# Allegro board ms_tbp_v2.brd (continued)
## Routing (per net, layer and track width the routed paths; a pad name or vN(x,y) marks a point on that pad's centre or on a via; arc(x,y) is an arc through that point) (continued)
PCIE_T2B_B1_RX_DN<13>: length 45.3
  TOP w0.127: J2.44 v1(46.11,13.96)
  LYR3 w0.127: J1.E3 26.55,9.79 26.79,9.79 26.87,9.87 26.87,26.2 27.46,26.78 31.45,26.78 33.43,24.8 33.43,21.85 41,14.28 42.91,14.28 43.08,14.11 43.72,13.47 45.62,13.47 v1(46.11,13.96)
PCIE_T2B_B1_RX_DN<14>: length 40.4
  TOP w0.127: J2.27 v1(44.84,11.42)
  LYR3 w0.127: J1.F2 28.55,11.09 28.77,11.09 28.87,11.18 28.87,24.91 29.45,25.49 30.51,25.49 30.75,25.49 32,24.25 32,20.43 41.49,10.93 44.35,10.93 v1(44.84,11.42)
PCIE_T2B_B1_RX_DN<15>: length 20.3
  TOP w0.127: J2.12 v1(46.11,8.88)
  LYR3 w0.127: J1.E1 30.55,9.79 30.91,9.79 35.02,5.68 41.8,5.68 44.51,8.39 45.62,8.39 v1(46.11,8.88)
PCIE_T2B_B1_RX_DP<0>: length 53.3
  TOP w0.127: J2.113 42.45,25.24 41.73,25.24 40.95,26.02 40.95,26.82 35.17,32.6 22.88,32.6 17.16,26.88 17.16,6.96 16.79,6.59 16.55,6.59 J1.B8
PCIE_T2B_B1_RX_DP<1>: length 54.2
  TOP w0.127: J1.A7 18.55,5.29 18.8,5.29 19.16,5.65 19.16,26.49 24.05,31.38 34.34,31.38 39.49,26.23 39.49,24.6 41.39,22.7 43.72,22.7 J2.98
PCIE_T2B_B1_RX_DP<2>: length 49.6
  TOP w0.127: J1.B6 20.55,6.59 20.8,6.59 21.15,6.94 21.15,26.36 24.95,30.16 33.57,30.16 38.23,25.5 38.23,23.8 41.86,20.16 42.45,20.16 J2.81
PCIE_T2B_B1_RX_DP<3>: length 50.6
  TOP w0.127: J1.A5 22.55,5.29 22.8,5.29 23.15,5.63 23.15,26.14 25.95,28.94 32.75,28.94 35.49,26.21 35.49,23.79 37.19,22.09 37.19,22.09 41.66,17.62 43.72,17.62 J2.66
PCIE_T2B_B1_RX_DP<4>: length 46
  TOP w0.127: J2.49 42.43,15.1 42.02,15.1 40.8,16.32 40.8,16.7 37.02,20.49 34.04,23.46 34.04,25.93 32.25,27.72 27.14,27.72 25.15,25.73 25.15,6.94 24.8,6.59 24.55,6.59 J1.B4
PCIE_T2B_B1_RX_DP<5>: length 49.6
  TOP w0.127: J2.34 43.72,12.54 41.68,12.54 40.86,13.35 40.86,14.14 38.2,16.8 34.53,16.8 32.65,18.68 32.65,25.6 31.77,26.48 28.35,26.48 27.65,26.48 27.16,25.99 27.16,25.92 27.16,25.92 27.16,5.65 26.8,5.29 26.55,5.29 J1.A3
PCIE_T2B_B1_RX_DP<6>: length 44.6
  TOP w0.127: J1.B2 28.55,6.59 28.8,6.59 29.16,6.95 29.16,24.75 29.63,25.21 30.8,25.21 31.31,24.7 31.31,18.24 34.09,15.46 37.67,15.46 39.94,13.19 39.94,12.56 40.77,11.72 40.77,10.55 41.33,10 42.45,10 J2.17
PCIE_T2B_B1_RX_DP<7>: length 15.5
  TOP w0.127: J1.A1 30.55,5.29 39.42,5.29 41.59,7.46 43.72,7.46 J2.2
PCIE_T2B_B1_RX_DP<8>: length 50.5
  TOP w0.127: J2.115 v1(44.84,25.39)
  LYR3 w0.127: v1(44.84,25.39) 44.35,25.88 41.66,25.88 35.85,31.69 21.91,31.69 17.13,26.91 17.13,12.57 17.1,12.54 17.1,11.09 16.8,10.79 16.55,10.79 J1.E8
PCIE_T2B_B1_RX_DP<9>: length 51.2
  TOP w0.127: J2.100 v1(46.11,22.85)
  LYR3 w0.127: J1.D7 18.55,9.49 18.82,9.49 19.14,9.81 19.14,26.87 22.93,30.66 34.76,30.66 41.16,24.26 42.48,24.26 43.4,23.34 45.62,23.34 v1(46.11,22.85)
PCIE_T2B_B1_RX_DP<10>: length 47
  TOP w0.127: J2.83 v1(44.84,20.31)
  LYR3 w0.127: v1(44.84,20.31) 44.35,20.8 42.01,20.8 37.71,25.1 37.71,25.99 34.07,29.63 24.57,29.63 21.13,26.19 21.13,11.12 20.8,10.79 20.55,10.79 J1.E6
PCIE_T2B_B1_RX_DP<11>: length 47.9
  TOP w0.127: J2.68 v1(46.11,17.77)
  LYR3 w0.127: v1(46.11,17.77) 45.62,18.26 43.23,18.26 42.43,19.06 41.55,19.06 35.86,24.75 35.86,25.75 33.02,28.59 25.51,28.59 23.16,26.24 23.16,9.77 22.89,9.49 22.55,9.49 J1.D5
PCIE_T2B_B1_RX_DP<12>: length 44.2
  TOP w0.127: J2.51 v1(44.84,15.23)
  LYR3 w0.127: J1.E4 24.55,10.79 24.8,10.79 25.16,11.15 25.16,25.93 26.78,27.55 32.13,27.55 34.31,25.37 34.31,22.77 41.36,15.72 44.35,15.72 v1(44.84,15.23)
PCIE_T2B_B1_RX_DP<13>: length 45.3
  TOP w0.127: J2.36 v1(46.11,12.69)
  LYR3 w0.127: J1.D3 26.55,9.49 26.91,9.49 27.16,9.75 27.16,26.07 27.58,26.49 31.32,26.49 33.14,24.68 33.14,21.73 40.88,13.99 42.79,13.99 43.6,13.18 45.62,13.18 v1(46.11,12.69)
PCIE_T2B_B1_RX_DP<14>: length 40.4
  TOP w0.127: J2.19 v1(44.84,10.15)
  LYR3 w0.127: v1(44.84,10.15) 44.35,10.64 41.37,10.64 31.7,20.31 31.7,24.12 30.63,25.2 29.57,25.2 29.16,24.79 29.16,11.06 28.89,10.79 28.55,10.79 J1.E2
PCIE_T2B_B1_RX_DP<15>: length 20.3
  TOP w0.127: J2.4 v1(46.11,7.61)
  LYR3 w0.127: v1(46.11,7.61) 45.62,8.1 44.63,8.1 41.92,5.39 34.9,5.39 30.79,9.49 30.55,9.49 J1.D1
PCIE_T2B_B2_RX_DN<0>: length 53.2
  TOP w0.127: J13.C8 237.55,6.89 237.66,6.89 237.85,7.08 237.85,26.46 244.56,33.17 256.03,33.17 262.26,26.95 262.26,26.15 262.86,25.54 263.45,25.54 J14.121
PCIE_T2B_B2_RX_DN<1>: length 54.3
  TOP w0.127: J13.B7 239.55,5.59 239.67,5.59 239.85,5.77 239.85,26.61 245.09,31.85 255.31,31.85 260.62,26.53 260.8,26.36 260.8,24.72 262.52,23 264.72,23 J14.106
PCIE_T2B_B2_RX_DN<2>: length 49.5
  TOP w0.127: J13.C6 241.55,6.89 241.67,6.89 241.85,7.06 241.85,26.49 245.9,30.55 254.61,30.55 259.53,25.63 259.53,24.21 263.27,20.46 263.45,20.46 J14.89
PCIE_T2B_B2_RX_DN<3>: length 50.9
  TOP w0.127: J13.B5 243.55,5.59 243.67,5.59 243.84,5.76 243.84,26.26 246.89,29.32 253.81,29.32 256.78,26.35 256.78,24.9 261.73,19.95 261.73,18.43 262.24,17.92 264.72,17.92 J14.74
PCIE_T2B_B2_RX_DN<4>: length 46.3
  TOP w0.127: J13.C4 245.55,6.89 245.67,6.89 245.85,7.07 245.85,25.86 248.07,28.08 253.32,28.08 255.38,26.03 255.38,24.52 260.31,19.6 260.31,17.85 262.77,15.38 263.45,15.38 J14.57
PCIE_T2B_B2_RX_DN<5>: length 48.7
  TOP w0.127: J14.42 264.72,12.84 263.58,12.84 262.44,13.98 262.44,13.99 259.3,17.13 256.45,17.13 253.93,19.65 253.93,22.5 253.93,22.5 253.93,25.75 252.9,26.78 249.47,26.78 248.53,26.78 247.86,26.11 247.86,26.05 247.86,26.04 247.86,5.77 247.67,5.59 247.55,5.59 J13.B3
PCIE_T2B_B2_RX_DN<6>: length 44
  TOP w0.127: J13.C2 249.55,6.89 249.67,6.89 249.86,7.07 249.86,24.87 250.5,25.52 251.92,25.52 252.62,24.82 252.62,19.11 255.82,15.91 258.64,15.91 261.88,12.68 261.88,11.21 262.79,10.3 263.45,10.3 J14.25
PCIE_T2B_B2_RX_DN<7>: length 15.5
  TOP w0.127: J13.B1 251.55,5.59 260.29,5.59 262.46,7.76 264.72,7.76 J14.10
PCIE_T2B_B2_RX_DN<8>: length 51.6
  TOP w0.127: J14.123 v1(265.84,26.66)
  LYR3 w0.127: v1(265.84,26.66) 265.35,26.17 262.78,26.17 255.64,33.31 244.12,33.31 237.84,27.03 237.84,11.24 237.68,11.09 237.55,11.09 J13.F8
PCIE_T2B_B2_RX_DN<9>: length 52.1
  TOP w0.127: J14.108 v1(267.11,24.12)
  LYR3 w0.127: J13.E7 239.55,9.79 239.7,9.79 239.85,9.94 239.85,26.99 244.84,31.98 254.85,31.98 262.28,24.55 263.6,24.55 264.52,23.63 266.62,23.63 v1(267.11,24.12)
PCIE_T2B_B2_RX_DN<10>: length 47.5
  TOP w0.127: J14.91 v1(265.84,21.58)
  LYR3 w0.127: J13.F6 241.55,11.09 241.68,11.09 241.84,11.24 241.84,26.31 246.13,30.61 254.51,30.61 258.83,26.29 259,26.12 259,25.22 263.13,21.09 265.35,21.09 v1(265.84,21.58)
PCIE_T2B_B2_RX_DN<11>: length 48.5
  TOP w0.127: J14.76 v1(267.11,19.04)
  LYR3 w0.127: v1(267.11,19.04) 266.62,18.55 263.84,18.55 259.49,22.9 258.74,22.9 257.36,24.28 257.36,25.66 253.59,29.43 246.93,29.43 243.87,26.36 243.87,9.89 243.76,9.79 243.55,9.79 J13.E5
PCIE_T2B_B2_RX_DN<12>: length 44
  TOP w0.127: J14.59 v1(265.84,16.5)
  LYR3 w0.127: J13.F4 245.55,11.09 245.68,11.09 245.87,11.27 245.87,26.05 247.74,27.93 253.16,27.93 256.04,25.05 256.21,24.88 256.21,22.78 262.98,16.01 265.35,16.01 v1(265.84,16.5)
PCIE_T2B_B2_RX_DN<13>: length 45.4
  TOP w0.127: J14.44 v1(267.11,13.96)
  LYR3 w0.127: v1(267.11,13.96) 266.62,13.47 262.82,13.47 261.4,14.9 261.39,14.9 254.91,21.38 254.91,24.32 254.74,24.49 252.35,26.88 248.56,26.88 247.87,26.2 247.87,9.87 247.79,9.79 247.55,9.79 J13.E3
PCIE_T2B_B2_RX_DN<14>: length 40.2
  TOP w0.127: J14.27 v1(265.84,11.42)
  LYR3 w0.127: v1(265.84,11.42) 265.35,10.93 262.88,10.93 253,20.81 253,24.25 251.75,25.49 251.51,25.49 250.45,25.49 249.87,24.91 249.87,11.18 249.77,11.09 249.55,11.09 J13.F2
PCIE_T2B_B2_RX_DN<15>: length 20.9
  TOP w0.127: J14.12 v1(267.11,8.88)
  LYR3 w0.127: v1(267.11,8.88) 266.62,8.39 265.5,8.39 262.79,5.68 255.09,5.68 252.59,8.18 252.59,9.27 252.08,9.79 251.55,9.79 J13.E1
PCIE_T2B_B2_RX_DP<0>: length 53.2
  TOP w0.127: J13.B8 237.55,6.59 237.79,6.59 238.16,6.96 238.16,26.33 244.69,32.86 255.91,32.86 261.95,26.82 261.95,26.02 262.73,25.24 263.45,25.24 J14.113
PCIE_T2B_B2_RX_DP<1>: length 54.3
  TOP w0.127: J13.A7 239.55,5.29 239.8,5.29 240.16,5.65 240.16,26.49 245.21,31.54 255.18,31.54 260.49,26.23 260.49,24.6 262.39,22.7 264.72,22.7 J14.98
PCIE_T2B_B2_RX_DP<2>: length 49.5
  TOP w0.127: J14.81 263.45,20.16 263.15,20.16 259.23,24.08 259.23,25.5 254.49,30.24 246.03,30.24 242.15,26.36 242.15,6.94 241.8,6.59 241.55,6.59 J13.B6
PCIE_T2B_B2_RX_DP<3>: length 50.9
  TOP w0.127: J14.66 264.72,17.62 262.11,17.62 261.42,18.31 261.42,19.82 256.47,24.78 256.47,26.23 253.69,29.01 247.02,29.01 244.15,26.14 244.15,5.63 243.8,5.29 243.55,5.29 J13.A5
PCIE_T2B_B2_RX_DP<4>: length 46.3
  TOP w0.127: J13.B4 245.55,6.59 245.8,6.59 246.15,6.94 246.15,25.73 248.2,27.78 253.2,27.78 255.07,25.9 255.07,24.4 260,19.47 260,17.72 262.65,15.08 263.45,15.08 J14.49
PCIE_T2B_B2_RX_DP<5>: length 48.7
  TOP w0.127: J14.34 264.72,12.54 263.45,12.54 262.14,13.86 262.14,13.86 259.17,16.83 256.32,16.83 253.63,19.52 253.63,22.63 253.63,25.62 252.77,26.48 249.35,26.48 248.65,26.48 248.16,25.99 248.16,25.92 248.16,25.92 248.16,5.65 247.8,5.29 247.55,5.29 J13.A3
PCIE_T2B_B2_RX_DP<6>: length 44
  TOP w0.127: J13.B2 249.55,6.59 249.8,6.59 250.16,6.95 250.16,24.75 250.63,25.21 251.8,25.21 252.31,24.7 252.31,18.99 255.69,15.61 258.52,15.61 261.58,12.55 261.58,11.09 262.67,10 263.45,10 J14.17
PCIE_T2B_B2_RX_DP<7>: length 15.5
  TOP w0.127: J14.2 264.72,7.46 262.59,7.46 260.42,5.29 251.55,5.29 J13.A1
PCIE_T2B_B2_RX_DP<8>: length 51.6
  TOP w0.127: J14.115 v1(265.84,25.39)
  LYR3 w0.127: J13.E8 237.55,10.79 237.8,10.79 238.13,11.12 238.13,26.91 244.24,33.02 255.52,33.02 262.66,25.88 265.35,25.88 v1(265.84,25.39)
PCIE_T2B_B2_RX_DP<9>: length 52.1
  TOP w0.127: J14.100 v1(267.11,22.85)
  LYR3 w0.127: J13.D7 239.55,9.49 239.82,9.49 240.14,9.81 240.14,26.87 244.96,31.68 254.73,31.68 262.16,24.26 263.48,24.26 264.4,23.34 266.62,23.34 v1(267.11,22.85)
PCIE_T2B_B2_RX_DP<10>: length 47.5
  TOP w0.127: J14.83 v1(265.84,20.31)
  LYR3 w0.127: J13.E6 241.55,10.79 241.8,10.79 242.13,11.12 242.13,26.19 246.26,30.31 254.39,30.31 258.71,25.99 258.71,25.1 263.01,20.8 265.35,20.8 v1(265.84,20.31)
PCIE_T2B_B2_RX_DP<11>: length 48.5
  TOP w0.127: J14.68 v1(267.11,17.77)
  LYR3 w0.127: v1(267.11,17.77) 266.62,18.26 263.72,18.26 259.37,22.61 258.62,22.61 257.07,24.16 257.07,25.54 253.47,29.14 247.05,29.14 244.16,26.24 244.16,9.77 243.89,9.49 243.55,9.49 J13.D5
PCIE_T2B_B2_RX_DP<12>: length 44
  TOP w0.127: J14.51 v1(265.84,15.23)
  LYR3 w0.127: v1(265.84,15.23) 265.35,15.72 262.86,15.72 255.92,22.66 255.92,24.76 255.83,24.84 253.04,27.63 247.86,27.63 246.16,25.93 246.16,11.15 245.8,10.79 245.55,10.79 J13.E4
PCIE_T2B_B2_RX_DP<13>: length 45.4
  TOP w0.127: J14.36 v1(267.11,12.69)
  LYR3 w0.127: J13.D3 247.55,9.49 247.91,9.49 248.16,9.75 248.16,26.07 248.68,26.59 252.23,26.59 254.62,24.2 254.62,21.26 261.27,14.61 261.28,14.61 262.7,13.18 266.62,13.18 v1(267.11,12.69)
PCIE_T2B_B2_RX_DP<14>: length 40.2
  TOP w0.127: J14.19 v1(265.84,10.15)
  LYR3 w0.127: v1(265.84,10.15) 265.35,10.64 262.75,10.64 252.7,20.69 252.7,24.12 251.63,25.2 251.51,25.2 250.57,25.2 250.16,24.79 250.16,11.06 249.89,10.79 249.55,10.79 J13.E2
PCIE_T2B_B2_RX_DP<15>: length 20.9
  TOP w0.127: J14.4 v1(267.11,7.61)
  LYR3 w0.127: J13.D1 251.55,9.49 251.96,9.49 252.3,9.15 252.3,8.06 254.97,5.39 255.21,5.39 262.91,5.39 265.62,8.1 266.62,8.1 v1(267.11,7.61)
PCIE_WAKE_B1_N: length 40.1
  TOP w0.127: J2.159 v1(49.92,31.74)
  LYR4 w0.13: v1(49.92,31.74) 49.59,31.41 49.59,31.19 49.35,30.95 45.85,30.95 45.47,30.57 45.47,30.31 45.07,29.91 44.61,29.91 43.28,28.58 40.88,28.58 39.5,27.2 26.74,27.2 25.15,25.62 25.15,15.59 J1.H4
PCIE_WAKE_B2_N: length 40.1
  TOP w0.127: J14.159 v1(270.92,31.74)
  LYR4 w0.13: v1(270.92,31.74) 270.59,31.41 270.59,31.19 270.35,30.95 266.85,30.95 266.47,30.57 266.47,30.31 266.07,29.91 265.61,29.91 264.28,28.58 261.88,28.58 260.5,27.2 247.74,27.2 246.15,25.62 246.15,15.59 J13.H4
PSU_B1_ALERT_N: length 196.5
  TOP w0.102: U1.S4 4.76,47 8.08,43.68 8.08,42.68 9.97,40.8 9.97,35.42 9.52,34.97 9.52,33.42 10.01,32.93 v1(11.36,32.93) ; J26.1 v1(87.56,48.48)
  LYR3 w0.13: v1(53.65,30.14) 52.76,30.14 51.72,31.18 51.72,31.89 51.32,32.3 45.22,32.3 43.18,34.33 14.21,34.33 12.81,32.93 v1(11.36,32.93) ; v1(117.13,23.79) 117.13,20.82 119.69,18.25 119.69,13.75 120.41,13.04 J7.G5 ; v1(86.93,25.91) 87.31,26.29 87.31,28.54 86.39,29.45 86.39,42.08 87.56,43.24 v1(87.56,48.48)
  LYR4 w0.13: J1.H7 17.99,14.54 17.08,15.46 17.08,26.2 16.72,26.56 14.99,26.56 12.28,29.27 12.28,32.02 v1(11.36,32.93)
  BOTTOM w0.102: v1(117.13,23.79) 116.24,24.68 89.77,24.68 88.54,25.91 v1(86.93,25.91) 86.9,25.88 86.2,25.88 79.99,32.1 57.21,32.1 55.25,30.14 v1(53.65,30.14)
PSU_B2_ALERT_N: length 514.6
  TOP w0.102: v1(308.52,48.5) 308.49,48.48 J29.1 ; J19.G5 341.42,13.08 340.39,14.11 340.39,20.23 340.04,20.59 340.04,21.4 340.47,21.83 342.5,21.83 343.16,21.17 v1(343.19,21.17)
  LYR3 w0.13: v1(53.73,33.31) 53.27,33.31 50.56,36.02 13.3,36.02 7.17,42.15 5.67,42.15 4.81,43.01 v1(4.76,43.01)
  LYR4 w0.13: J13.H7 240.06,13.48 240.06,4.23 240.98,3.31 252.71,3.31 255.2,5.8 266.12,5.8 268.28,3.64 317.94,3.64 318.96,4.66 318.96,12.2 327.26,20.5 v1(327.26,23.15)
  BOTTOM w0.102: v1(53.73,33.31) 53.78,33.26 54.92,33.26 56.27,34.61 79.61,34.61 97.47,52.46 266.58,52.46 267.9,51.14 304.15,51.14 306.79,48.5 v1(308.52,48.5) 308.52,36.16 307.63,35.27 307.63,33.46 308.52,32.58 308.52,28.64 312.45,24.7 316.62,24.7 318.17,23.15 v1(327.26,23.15) 327.51,23.41 340.49,23.41 342.72,21.17 v1(343.19,21.17) ; v1(4.76,43.01) U1.S9
SAS_B1_RX1N: length 33.9
  BOTTOM w0.107: J11.E1 175.16,9.86 arc(175.29,9.77) 175.45,9.74 176.82,9.74 arc(176.99,9.77) 177.13,9.87 180.86,13.6 arc(181.57,14.67) 181.83,15.94 arc(181.94,16.5) 182.26,16.98 183.48,18.2 arc(184.15,19.21) 184.39,20.41 184.39,25.85 arc(184.15,27.07) 183.45,28.11 183.2,28.37 arc(182.6,29.27) 182.38,30.33 182.38,30.73 arc(182.21,31.15) 181.78,31.33 179.01,31.33 arc(178.38,31.59) 178.12,32.23 178.12,32.33 arc(178.2,32.74) 178.43,33.09 178.64,33.29 arc(178.7,33.35) 178.76,33.39 178.79,33.4 arc(178.84,33.46) 178.83,33.55 J12.1B5
SAS_B1_RX1P: length 34.6
  BOTTOM w0.107: J11.D1 175.1,9.16 arc(175.26,9.27) 175.45,9.31 175.79,9.31 175.99,9.11 176.32,9.11 176.52,9.31 176.82,9.31 arc(177.15,9.37) 177.43,9.56 177.61,9.74 arc(177.67,9.77) 177.73,9.74 arc(177.9,9.67) 178.07,9.74 178.24,9.91 arc(178.28,10.02) 178.24,10.12 arc(178.19,10.24) 178.24,10.37 181.16,13.29 arc(181.98,14.51) 182.26,15.94 arc(182.34,16.34) 182.56,16.67 183.78,17.89 arc(184.55,19.05) 184.83,20.41 184.83,25.85 arc(184.55,27.24) 183.76,28.42 183.5,28.68 arc(183,29.43) 182.82,30.33 182.82,30.73 arc(182.52,31.46) 181.78,31.77 179.01,31.77 arc(178.69,31.9) 178.55,32.23 178.55,32.33 arc(178.6,32.57) 178.74,32.78 178.94,32.99 arc(178.96,33) 178.97,33.01 178.99,33.02 arc(179.07,33.03) 179.14,32.98 J12.1B4
SAS_B1_RX2N: length 26.9
  BOTTOM w0.107: J12.1A5 178.83,37.35 arc(178.84,37.26) 178.79,37.2 178.76,37.19 arc(178.7,37.15) 178.64,37.09 178.45,36.91 arc(178.26,36.63) 178.2,36.3 178.2,36.03 arc(177.98,35.51) 177.46,35.3 175.67,35.3 arc(174.88,34.97) 174.56,34.18 174.56,27.38 arc(174.51,27.15) 174.38,26.96 arc(174.18,26.65) 174.1,26.29 174.1,18.18 arc(174.02,17.75) 173.77,17.39 arc(173.6,17.13) 173.55,16.83 173.55,15.43 arc(173.49,15.3) 173.37,15.25 173.24,15.25 arc(172.91,15.39) 172.78,15.71 J11.I2
SAS_B1_RX2P: length 28
  BOTTOM w0.107: J12.1A4 179.14,36.78 arc(179.07,36.83) 178.99,36.82 178.97,36.81 arc(178.96,36.8) 178.94,36.79 178.76,36.6 arc(178.67,36.46) 178.63,36.3 178.63,36.03 arc(178.29,35.2) 177.46,34.86 175.67,34.86 arc(175.19,34.66) 174.99,34.18 174.99,27.38 arc(174.91,26.99) 174.69,26.66 arc(174.58,26.49) 174.54,26.29 174.54,21.04 arc(174.58,20.95) 174.67,20.92 174.68,20.92 arc(174.81,20.86) 174.87,20.73 174.87,20.51 arc(174.81,20.38) 174.69,20.33 arc(174.58,20.29) 174.54,20.18 174.54,19.37 arc(174.57,19.3) 174.65,19.27 174.68,19.27 arc(174.81,19.21) 174.87,19.08 174.87,18.78 arc(174.81,18.66) 174.69,18.61 arc(174.58,18.56) 174.54,18.46 174.54,18.18 arc(174.42,17.59) 174.08,17.08 arc(174.01,16.97) 173.98,16.83 173.98,16.56 174.18,16.37 174.18,15.96 173.98,15.76 173.98,15.43 arc(173.8,15) 173.37,14.82 173.24,14.82 arc(172.91,14.68) 172.78,14.36 J11.H2
SAS_B1_RX3N: length 46
  LYR6 w0.112: J12.1B8 176.6,33.51 arc(176.61,33.43) 176.56,33.36 176.46,33.31 arc(176.44,33.28) 176.41,33.26 arc(176.4,33.24) 176.38,33.23 176.12,32.96 arc(175.94,32.7) 175.88,32.39 arc(176.18,31.67) 176.89,31.38 181.99,31.38 arc(182.31,31.25) 182.44,30.93 182.44,10.66 arc(182.12,9.02) 181.19,7.63 177.8,4.24 arc(177.12,3.79) 176.33,3.63 174.24,3.63 arc(174.04,3.72) 173.95,3.92 173.95,6.18 arc(173.77,6.63) 173.32,6.82 173.3,6.82 arc(172.93,6.97) J11.C2
SAS_B1_RX3P: length 46.9
  LYR6 w0.112: J12.1B7 176.87,33.01 arc(176.8,33.07) 176.72,33.06 176.67,33.03 arc(176.65,33.01) 176.64,32.99 176.36,32.72 arc(176.26,32.57) 176.23,32.39 arc(176.42,31.92) 176.89,31.72 181.99,31.72 arc(182.55,31.49) 182.79,30.93 182.79,10.66 arc(182.43,8.89) 181.43,7.39 181.02,6.98 181.02,6.67 180.75,6.39 180.43,6.39 180.15,6.11 arc(180.12,6.03) 180.15,5.95 180.15,5.95 arc(180.19,5.87) 180.15,5.79 179.74,5.38 arc(179.68,5.35) 179.61,5.38 179.59,5.39 arc(179.51,5.43) 179.44,5.39 178.87,4.83 arc(178.84,4.75) 178.87,4.67 178.88,4.67 arc(178.91,4.59) 178.88,4.52 178.45,4.09 arc(178.39,4.06) 178.33,4.09 178.31,4.11 arc(178.23,4.14) 178.15,4.11 178.04,4 arc(177.25,3.47) 176.33,3.29 174.24,3.29 arc(173.79,3.48) 173.61,3.92 173.61,6.18 arc(173.52,6.39) 173.32,6.48 arc(172.94,6.32) J11.B2
SAS_B1_RX4N: length 31.7
  BOTTOM w0.107: J11.E3 170.78,10.22 arc(170.91,9.89) 171.24,9.74 arc(171.47,9.83) 171.56,10.06 171.56,20.75 arc(171.7,21.47) 172.11,22.08 172.66,22.63 arc(172.75,22.77) 172.78,22.92 172.78,33.54 arc(173.05,34.88) 173.81,36.02 173.89,36.1 arc(174.32,36.39) 174.82,36.49 175.58,36.49 arc(175.94,36.58) 176.19,36.87 arc(176.29,37.03) 176.44,37.15 176.54,37.2 arc(176.59,37.26) 176.58,37.35 J12.1A8
SAS_B1_RX4P: length 32.3
  BOTTOM w0.107: J11.D3 170.78,9.08 arc(170.85,9.24) 171,9.31 171.23,9.31 arc(171.25,9.31) 171.27,9.31 arc(171.78,9.52) 171.99,10.03 171.99,17.51 arc(172.02,17.58) 172.1,17.61 172.14,17.61 arc(172.23,17.65) 172.27,17.74 172.27,18.12 arc(172.23,18.21) 172.14,18.25 172.13,18.25 arc(172.03,18.29) 171.99,18.38 171.99,20.66 arc(172.12,21.3) 172.48,21.84 172.97,22.33 arc(173.15,22.6) 173.22,22.92 173.22,33.54 arc(173.45,34.72) 174.12,35.72 174.2,35.8 arc(174.48,35.99) 174.82,36.05 175.57,36.05 arc(176.18,36.22) 176.59,36.7 arc(176.61,36.74) 176.65,36.77 176.74,36.82 arc(176.82,36.83) 176.89,36.78 J12.1A7
SAS_B1_RX5N: length 24.4
  BOTTOM w0.107: J12.2B5 167.83,33.55 arc(167.84,33.46) 167.79,33.4 167.76,33.39 arc(167.7,33.35) 167.64,33.29 167.44,33.1 arc(167.17,32.68) 167.07,32.19 arc(167.33,31.57) 167.95,31.31 170.98,31.31 arc(171.25,31.2) 171.36,30.93 171.36,24.36 arc(171.18,23.48) 170.68,22.73 169.84,21.88 arc(169.65,21.6) 169.58,21.27 169.58,15.48 arc(169.52,15.34) 169.38,15.28 169.28,15.28 arc(169.24,15.28) 169.19,15.27 arc(168.9,15.37) 168.78,15.64 J11.I4
SAS_B1_RX5P: length 25.5
  BOTTOM w0.107: J12.2B4 168.14,32.98 arc(168.07,33.03) 167.99,33.02 167.97,33.01 arc(167.96,33) 167.94,32.99 167.75,32.79 arc(167.57,32.52) 167.5,32.19 arc(167.64,31.87) 167.95,31.74 170.98,31.74 arc(171.56,31.51) 171.79,30.93 171.79,24.36 arc(171.58,23.31) 170.99,22.42 170.14,21.58 arc(170.05,21.43) 170.02,21.27 170.02,20.12 arc(170.04,20.06) 170.11,20.03 arc(170.28,19.96) 170.35,19.79 170.35,19.57 arc(170.29,19.45) 170.17,19.39 arc(170.06,19.35) 170.02,19.24 170.02,18.58 arc(170.06,18.47) 170.17,18.43 170.19,18.43 arc(170.32,18.38) 170.37,18.25 170.37,17.95 arc(170.31,17.8) 170.17,17.74 arc(170.06,17.7) 170.02,17.59 170.02,16.96 170.21,16.76 170.21,16.39 170.02,16.2 170.02,15.48 arc(169.83,15.03) 169.38,14.84 169.28,14.84 arc(169.26,14.84) 169.23,14.84 arc(168.91,14.68) J11.H4
SAS_B1_RX6N: length 46.8
  BOTTOM w0.107: J12.2A5 167.83,37.35 arc(167.9,37.29) 167.98,37.3 168.06,37.35 arc(168.07,37.35) 168.08,37.36 168.14,37.43 arc(168.28,37.64) 168.33,37.88 arc(168.65,38.66) 169.43,38.98 170.65,38.98 arc(171.47,38.64) 171.82,37.81 171.82,36.19 arc(171.48,35.38) 170.67,35.04 169.8,35.04 arc(169.12,35.03) 168.44,35 arc(168.25,34.96) 168.07,34.89 arc(167.87,34.82) 167.65,34.8 163.62,34.8 arc(162.56,34.36) 162.12,33.29 162.12,21.09 arc(162.25,20.77) 162.57,20.64 164.88,20.64 arc(165.67,20.31) 166,19.52 166,9.92 arc(166.05,9.79) 166.18,9.74 166.36,9.74 arc(166.66,9.86) 166.78,10.16 J11.E5
SAS_B1_RX6P: length 47.5
  BOTTOM w0.107: J11.D5 166.78,8.88 arc(166.66,9.18) 166.36,9.31 166.18,9.31 arc(165.75,9.49) 165.57,9.92 165.57,17.84 arc(165.54,17.91) 165.46,17.95 165.41,17.95 arc(165.32,17.98) 165.28,18.08 165.28,18.44 arc(165.31,18.52) 165.39,18.55 arc(165.52,18.61) 165.57,18.73 165.57,19.52 arc(165.37,20) 164.88,20.2 162.57,20.2 arc(161.94,20.46) 161.68,21.09 161.68,21.25 arc(161.65,21.33) 161.57,21.36 161.48,21.36 arc(161.39,21.39) 161.35,21.48 161.35,21.81 arc(161.39,21.9) 161.48,21.93 161.57,21.93 arc(161.65,21.96) 161.68,22.04 161.68,23.76 arc(161.67,23.81) 161.65,23.85 161.5,23.99 161.5,24.57 161.65,24.72 arc(161.67,24.76) 161.68,24.81 161.68,33.29 arc(162.25,34.66) 163.62,35.23 167.65,35.23 arc(167.77,35.25) 167.89,35.28 arc(168.13,35.38) 168.38,35.43 arc(169.09,35.46) 169.8,35.47 170.67,35.47 arc(171.17,35.68) 171.38,36.19 171.38,37.81 arc(171.17,38.33) 170.65,38.54 169.43,38.54 arc(168.96,38.35) 168.77,37.88 arc(168.68,37.47) 168.45,37.12 168.39,37.06 arc(168.33,37) 168.26,36.96 168.18,36.92 arc(168.13,36.86) 168.14,36.78 J12.2A4
SAS_B1_RX7N: length 27
  LYR6 w0.112: J11.I6 164.38,15.34 arc(164.21,15.23) 164.02,15.19 163.62,15.19 arc(163.18,15.28) 162.82,15.52 arc(162.3,16.3) 162.12,17.21 162.12,19.42 arc(162.14,19.47) 162.19,19.49 162.2,19.49 arc(162.3,19.54) 162.35,19.64 162.35,20.06 arc(162.3,20.16) 162.2,20.2 arc(162.14,20.23) 162.12,20.29 162.12,21.18 arc(162.15,21.25) 162.22,21.28 arc(162.31,21.32) 162.35,21.41 162.35,21.97 arc(162.31,22.05) 162.23,22.09 162.23,22.09 arc(162.15,22.12) 162.12,22.2 162.12,22.92 arc(162.14,22.98) 162.2,23.01 arc(162.29,23.05) 162.33,23.14 162.33,23.58 arc(162.29,23.68) 162.2,23.72 arc(162.14,23.74) 162.12,23.8 162.12,24.95 162.35,25.19 162.35,25.5 162.12,25.73 162.12,29.11 162.12,29.11 arc(162.62,31.63) 164.05,33.77 arc(164.17,33.95) 164.21,34.17 164.21,34.28 arc(164.37,34.67) 164.77,34.84 165.7,34.84 arc(165.88,34.8) 166.03,34.7 166.1,34.63 arc(166.15,34.56) 166.16,34.48 166.16,34.25 arc(166.09,33.88) 165.88,33.56 165.82,33.51 arc(165.81,33.49) 165.79,33.49 165.75,33.46 arc(165.67,33.46) 165.6,33.51 J12.2B8
SAS_B1_RX7P: length 28
  LYR6 w0.112: J11.H6 164.45,14.67 arc(164.25,14.8) 164.02,14.85 163.62,14.85 arc(163.05,14.96) 162.57,15.28 arc(161.98,16.16) 161.77,17.21 161.77,29.11 arc(162.3,31.76) 163.8,34.01 arc(163.85,34.08) 163.87,34.17 163.87,34.28 arc(164.13,34.92) 164.77,35.18 165.7,35.18 arc(166.01,35.12) 166.27,34.94 166.34,34.87 arc(166.46,34.69) 166.5,34.48 166.5,34.25 arc(166.4,33.75) 166.12,33.32 166.06,33.26 arc(166.01,33.22) 165.95,33.18 165.91,33.16 arc(165.86,33.1) 165.87,33.01 J12.2B7
SAS_B1_RX8N: length 41.2
  LYR6 w0.112: J11.C6 164.78,7.33 arc(164.63,6.97) 164.27,6.82 163.44,6.82 163.4,6.86 162.94,6.86 162.9,6.82 162.24,6.82 arc(161.34,7.19) 160.97,8.09 160.97,8.54 arc(160.99,8.61) 161.05,8.63 arc(161.16,8.67) 161.2,8.78 161.2,9.04 arc(161.15,9.15) 161.05,9.19 arc(160.99,9.21) 160.97,9.27 160.97,10.62 arc(161,10.69) 161.06,10.71 arc(161.16,10.75) 161.2,10.85 161.2,11.27 arc(161.16,11.37) 161.06,11.41 arc(160.99,11.44) 160.97,11.5 160.97,12.65 arc(160.99,12.72) 161.06,12.74 arc(161.16,12.78) 161.2,12.88 161.2,13.3 arc(161.15,13.41) 161.05,13.45 arc(160.99,13.48) 160.97,13.54 160.97,14.33 arc(160.99,14.38) 161.04,14.4 arc(161.15,14.45) 161.2,14.56 161.2,14.86 arc(161.15,14.98) 161.03,15.03 arc(160.99,15.05) 160.97,15.1 160.97,31.24 arc(161.26,32.73) 162.11,34 162.86,34.75 arc(163.53,35.75) 163.76,36.92 163.76,37.03 arc(163.87,37.56) 164.16,38 164.46,38.3 arc(164.9,38.59) 165.42,38.7 arc(165.76,38.63) 166.04,38.44 166.27,38.21 arc(166.36,37.99) 166.27,37.77 165.8,37.3 arc(165.79,37.29) 165.78,37.28 165.75,37.26 arc(165.67,37.26) 165.6,37.31 J12.2A8
SAS_B1_RX8P: length 42.1
  LYR6 w0.112: J11.B6 164.78,5.97 arc(164.63,6.33) 164.27,6.48 162.24,6.48 arc(161.1,6.95) 160.62,8.09 160.62,31.24 arc(160.95,32.86) 161.87,34.24 162.62,34.99 arc(163.21,35.88) 163.42,36.92 163.42,37.03 arc(163.55,37.69) 163.92,38.24 164.22,38.54 arc(164.77,38.91) 165.42,39.04 arc(165.89,38.95) 166.28,38.68 166.51,38.45 arc(166.71,37.99) 166.51,37.52 166.05,37.05 arc(166,37.01) 165.94,36.98 165.91,36.96 arc(165.86,36.9) 165.87,36.81 J12.2A7
SAS_B1_TX1N: length 23.7
  LYR6 w0.112: J12.1D5 178.85,25.91 arc(178.86,25.83) 178.81,25.76 178.72,25.71 arc(178.67,25.68) 178.61,25.63 178.19,25.21 arc(177.78,24.59) 177.63,23.86 177.63,7.05 arc(177.57,6.72) 177.38,6.44 177,6.06 arc(176.39,5.65) 175.68,5.51 175.25,5.51 arc(174.92,5.65) 174.78,5.98 J11.B1
SAS_B1_TX1P: length 24.6
  LYR6 w0.112: J11.A1 174.78,4.7 arc(174.92,5.03) 175.25,5.17 175.68,5.17 arc(176.53,5.34) 177.24,5.82 177.62,6.2 arc(177.89,6.59) 177.98,7.05 177.98,7.32 arc(178,7.38) 178.07,7.4 arc(178.16,7.44) 178.2,7.54 178.2,7.85 arc(178.17,7.93) 178.09,7.96 178.09,7.96 arc(178.01,8) 177.98,8.07 177.98,8.89 arc(178.01,8.97) 178.09,9 arc(178.17,9.04) 178.2,9.12 178.2,9.5 arc(178.16,9.6) 178.07,9.64 arc(178,9.67) 177.98,9.73 177.98,10.61 178.17,10.8 178.17,11.11 177.98,11.3 177.98,23.86 arc(178.1,24.46) 178.44,24.97 178.86,25.39 arc(178.87,25.4) 178.88,25.41 178.97,25.46 arc(179.05,25.47) 179.12,25.41 J12.1D4
SAS_B1_TX2N: length 23.1
  BOTTOM w0.107: J12.1C5 178.83,29.75 arc(178.84,29.66) 178.79,29.6 178.71,29.56 arc(178.64,29.52) 178.58,29.46 178.57,29.45 arc(178.27,29.08) 178.08,28.65 arc(178.38,27.8) 179.2,27.44 179.97,27.44 arc(180.81,27.28) 181.52,26.8 181.99,26.33 arc(182.3,25.87) 182.4,25.34 182.4,23.3 arc(181.91,20.81) 180.49,18.69 175.83,14.03 arc(175.75,13.98) 175.65,13.96 175.26,13.96 arc(174.92,14.1) J11.H1
SAS_B1_TX2P: length 23.6
  BOTTOM w0.107: J12.1C4 179.14,29.18 arc(179.07,29.23) 178.99,29.22 178.91,29.18 arc(178.9,29.17) 178.89,29.16 178.87,29.14 arc(178.66,28.87) 178.51,28.57 arc(178.71,28.08) 179.2,27.88 179.97,27.88 arc(180.98,27.68) 181.83,27.11 182.3,26.64 arc(182.7,26.04) 182.84,25.34 182.84,23.3 arc(182.31,20.64) 180.8,18.39 177.94,15.52 177.94,15.28 177.64,14.99 177.4,14.99 177.11,14.7 177.11,14.4 176.87,14.16 176.57,14.16 176.14,13.73 arc(175.91,13.58) 175.65,13.52 175.26,13.52 arc(174.92,13.38) J11.G1
SAS_B1_TX3N: length 18.3
  LYR6 w0.112: J11.F2 172.78,11.36 arc(172.89,11.1) 173.14,11 173.32,11 arc(173.52,11.08) 173.61,11.29 173.61,23.53 arc(173.7,24) 173.97,24.39 174.04,24.46 arc(174.51,24.78) 175.07,24.89 175.17,24.89 arc(175.59,24.98) 175.94,25.21 176.36,25.63 arc(176.42,25.68) 176.47,25.71 176.56,25.76 arc(176.61,25.83) 176.6,25.91 J12.1D8
SAS_B1_TX3P: length 18.8
  LYR6 w0.112: J12.1D7 176.87,25.41 arc(176.8,25.47) 176.72,25.46 176.63,25.41 arc(176.62,25.4) 176.61,25.39 176.19,24.97 arc(175.72,24.66) 175.17,24.55 175.07,24.55 arc(174.64,24.46) 174.28,24.22 174.21,24.15 arc(174.02,23.87) 173.95,23.53 173.95,18.54 174.01,18.47 174.01,18.12 173.95,18.06 173.95,17.36 arc(173.98,17.29) 174.06,17.25 arc(174.15,17.22) 174.18,17.13 174.18,16.8 arc(174.14,16.7) 174.05,16.67 arc(173.98,16.64) 173.95,16.57 173.95,11.29 arc(173.77,10.84) 173.32,10.66 173.14,10.66 arc(172.89,10.55) 172.78,10.3 J11.E2
SAS_B1_TX4N: length 19.2
  LYR6 w0.112: J12.1C8 176.6,29.71 arc(176.61,29.63) 176.56,29.56 176.52,29.54 arc(176.46,29.5) 176.41,29.46 175.89,28.94 arc(175.78,28.87) 175.65,28.84 arc(175.35,28.78) 175.09,28.61 174.32,27.84 arc(172.3,24.82) 171.59,21.25 171.59,14.24 arc(171.49,14) 171.26,13.91 arc(170.92,14.05) 170.78,14.39 J11.H3
SAS_B1_TX4P: length 19.8
  LYR6 w0.112: J11.G3 170.78,13.08 arc(170.92,13.42) 171.26,13.56 arc(171.74,13.76) 171.93,14.24 171.93,17.66 arc(171.96,17.72) 172.02,17.74 arc(172.14,17.79) 172.19,17.91 172.19,18.23 arc(172.14,18.35) 172.03,18.39 arc(171.96,18.42) 171.93,18.49 171.93,19.22 172.03,19.32 172.03,19.78 171.93,19.89 171.93,21.25 arc(172.62,24.69) 174.56,27.6 175.33,28.36 arc(175.48,28.46) 175.65,28.5 arc(175.91,28.55) 176.13,28.7 176.65,29.22 arc(176.66,29.23) 176.68,29.24 176.72,29.26 arc(176.8,29.27) 176.87,29.21 J12.1C7
SAS_B1_TX5N: length 17.3
  LYR6 w0.112: J12.2D5 167.85,25.91 arc(167.86,25.83) 167.81,25.76 167.77,25.74 arc(167.71,25.7) 167.66,25.66 167.53,25.53 arc(167.3,25.19) 167.22,24.78 167.22,24.6 arc(167.45,23.47) 168.08,22.52 arc(169.19,20.86) 169.58,18.9 169.58,11.26 arc(169.51,11.09) 169.33,11.01 169.31,11.01 arc(168.93,11.17) J11.F4
SAS_B1_TX5P: length 17.7
  LYR6 w0.112: J12.2D4 168.12,25.41 arc(168.05,25.47) 167.97,25.46 167.93,25.44 arc(167.91,25.43) 167.9,25.42 167.78,25.29 arc(167.62,25.06) 167.56,24.78 167.56,24.6 arc(167.76,23.6) 168.33,22.76 arc(169.51,20.99) 169.93,18.9 169.93,18.14 169.96,18.11 169.96,17.68 169.93,17.64 169.93,17.23 arc(169.95,17.16) 170.02,17.13 arc(170.12,17.09) 170.16,17 170.16,16.61 arc(170.11,16.5) 170.01,16.46 arc(169.95,16.44) 169.93,16.38 169.93,11.26 arc(169.75,10.84) 169.33,10.67 169.31,10.67 arc(168.93,10.51) J11.E4
SAS_B1_TX6N: length 31.8
  BOTTOM w0.107: J12.2C5 167.83,29.75 arc(167.84,29.66) 167.79,29.6 167.69,29.55 arc(167.51,29.41) 167.38,29.21 arc(167.29,29.05) 167.17,28.9 167.03,28.76 arc(166.79,28.39) 166.7,27.96 166.7,27.9 arc(166.64,27.76) 166.5,27.7 165.37,27.7 arc(164.86,27.6) 164.43,27.31 164.15,27.03 arc(163.47,26.02) 163.23,24.83 163.23,23.2 arc(163.37,22.52) 163.75,21.95 163.77,21.93 arc(164.13,21.69) 164.57,21.6 166.94,21.6 arc(167.37,21.42) 167.55,20.99 167.55,5.75 arc(167.49,5.61) 167.35,5.55 167.22,5.55 arc(166.91,5.68) 166.78,5.99 J11.B5
SAS_B1_TX6P: length 32.7
  BOTTOM w0.107: J11.A5 166.78,4.67 arc(166.91,4.99) 167.22,5.12 167.35,5.12 arc(167.8,5.3) 167.99,5.75 167.99,17.65 arc(168.01,17.71) 168.08,17.74 168.09,17.74 arc(168.23,17.8) 168.29,17.94 168.29,18.17 arc(168.23,18.32) 168.08,18.38 arc(168.01,18.4) 167.99,18.47 167.99,18.88 arc(168.02,18.97) 168.11,19.01 168.21,19.01 arc(168.28,19.04) 168.31,19.12 168.31,19.47 arc(168.27,19.58) 168.16,19.62 168.14,19.62 arc(168.03,19.67) 167.99,19.77 167.99,20.99 arc(167.68,21.73) 166.94,22.03 164.57,22.03 arc(164.3,22.09) 164.07,22.24 164.06,22.25 arc(163.77,22.69) 163.67,23.2 163.67,24.83 arc(163.87,25.85) 164.45,26.72 164.74,27.01 arc(165.03,27.2) 165.37,27.27 166.5,27.27 arc(166.95,27.45) 167.13,27.9 167.13,27.96 arc(167.19,28.23) 167.34,28.45 167.47,28.59 arc(167.65,28.8) 167.78,29.04 arc(167.83,29.12) 167.9,29.17 167.99,29.22 arc(168.07,29.23) 168.14,29.18 J12.2C4
SAS_B1_TX7N: length 14.8
  LYR6 w0.112: J12.2D8 165.6,25.91 arc(165.61,25.83) 165.56,25.76 165.52,25.74 arc(165.46,25.7) 165.41,25.66 165.13,25.38 arc(164.99,25.16) 164.93,24.9 164.93,24.88 arc(165.04,24.35) 165.34,23.9 165.56,23.68 arc(165.74,23.42) 165.8,23.1 165.8,22.96 arc(165.89,22.52) 166.14,22.15 167.43,20.85 arc(167.55,20.68) 167.59,20.47 167.59,14.08 arc(167.54,13.96) 167.41,13.91 167.27,13.91 arc(166.92,14.05) 166.78,14.4 J11.H5
SAS_B1_TX7P: length 15.2
  LYR6 w0.112: J11.G5 166.78,13.07 arc(166.92,13.42) 167.27,13.56 167.41,13.56 arc(167.78,13.72) 167.93,14.08 167.93,17.99 arc(167.96,18.06) 168.03,18.08 arc(168.12,18.12) 168.16,18.22 168.16,18.64 arc(168.12,18.75) 168.01,18.79 arc(167.95,18.82) 167.93,18.87 167.93,19.44 167.97,19.48 167.97,19.95 167.93,19.99 167.93,20.47 arc(167.86,20.81) 167.67,21.09 166.38,22.39 arc(166.2,22.65) 166.14,22.96 166.14,23.1 arc(166.05,23.55) 165.8,23.93 165.58,24.14 arc(165.36,24.48) 165.28,24.88 165.28,24.9 arc(165.3,25.03) 165.37,25.14 165.66,25.42 arc(165.67,25.43) 165.68,25.44 165.72,25.46 arc(165.8,25.47) 165.87,25.41 J12.2D7
SAS_B1_TX8N: length 22.5
  LYR6 w0.112: J12.2C8 165.6,29.71 arc(165.61,29.63) 165.56,29.56 165.09,29.09 arc(164.84,28.93) 164.55,28.87 164.16,28.87 arc(163.56,28.62) 163.31,28.02 163.31,26.84 163.31,22.5 arc(163.46,21.73) 163.9,21.08 165.15,19.83 arc(165.48,19.33) 165.6,18.75 165.6,17.09 165.6,11.21 arc(165.54,11.07) 165.39,11.01 165.31,11.01 arc(164.93,11.17) J11.F6
SAS_B1_TX8P: length 23
  LYR6 w0.112: J12.2C7 165.87,29.21 arc(165.8,29.27) 165.72,29.26 165.73,29.25 165.33,28.85 arc(164.97,28.61) 164.55,28.52 164.16,28.52 arc(163.8,28.38) 163.65,28.02 163.65,26.84 163.65,22.5 arc(163.78,21.86) 164.14,21.32 165.39,20.07 arc(165.8,19.47) 165.94,18.75 165.94,18.11 165.98,18.06 165.98,17.61 165.94,17.56 165.94,17.09 arc(165.97,17.02) 166.04,16.99 arc(166.13,16.95) 166.17,16.86 166.17,16.49 arc(166.12,16.38) 166.02,16.34 arc(165.96,16.32) 165.94,16.26 165.94,11.21 arc(165.78,10.83) 165.39,10.67 165.26,10.67 arc(165.14,10.64) 165.03,10.57 164.91,10.45 arc(164.81,10.31) J11.E6
SAS_B2_RX1N: length 33.9
  BOTTOM w0.107: J24.1B5 399.83,33.55 arc(399.84,33.46) 399.79,33.4 399.76,33.39 arc(399.7,33.35) 399.64,33.29 399.43,33.09 arc(399.2,32.74) 399.12,32.33 399.12,32.23 arc(399.38,31.59) 400.01,31.33 402.78,31.33 arc(403.21,31.15) 403.38,30.73 403.38,30.33 arc(403.6,29.27) 404.2,28.37 404.45,28.11 arc(405.15,27.07) 405.39,25.85 405.39,20.41 arc(405.15,19.21) 404.48,18.2 403.26,16.98 arc(402.94,16.5) 402.83,15.94 arc(402.57,14.67) 401.86,13.6 398.13,9.87 arc(397.99,9.77) 397.82,9.74 396.45,9.74 arc(396.29,9.77) 396.16,9.86 J23.E1
SAS_B2_RX1P: length 34.6
  BOTTOM w0.107: J23.D1 396.1,9.16 arc(396.26,9.27) 396.45,9.31 396.79,9.31 396.99,9.11 397.32,9.11 397.52,9.31 397.82,9.31 arc(398.15,9.37) 398.43,9.56 398.61,9.74 arc(398.67,9.77) 398.73,9.74 arc(398.9,9.67) 399.07,9.74 399.24,9.91 arc(399.28,10.02) 399.24,10.12 arc(399.19,10.24) 399.24,10.37 402.16,13.29 arc(402.98,14.51) 403.26,15.94 arc(403.34,16.34) 403.56,16.67 404.78,17.89 arc(405.55,19.05) 405.83,20.41 405.83,25.85 arc(405.55,27.24) 404.76,28.42 404.5,28.68 arc(404,29.43) 403.82,30.33 403.82,30.73 arc(403.52,31.46) 402.78,31.77 400.01,31.77 arc(399.69,31.9) 399.55,32.23 399.55,32.33 arc(399.6,32.57) 399.74,32.78 399.94,32.99 arc(399.96,33) 399.97,33.01 399.99,33.02 arc(400.07,33.03) 400.14,32.98 J24.1B4
SAS_B2_RX2N: length 26.9
  BOTTOM w0.107: J24.1A5 399.83,37.35 arc(399.84,37.26) 399.79,37.2 399.76,37.19 arc(399.7,37.15) 399.64,37.09 399.45,36.91 arc(399.26,36.63) 399.2,36.3 399.2,36.03 arc(398.98,35.51) 398.46,35.3 396.67,35.3 arc(395.88,34.97) 395.56,34.18 395.56,27.38 arc(395.51,27.15) 395.38,26.96 arc(395.18,26.65) 395.1,26.29 395.1,18.18 arc(395.02,17.75) 394.77,17.39 arc(394.6,17.13) 394.55,16.83 394.55,15.43 arc(394.49,15.3) 394.37,15.25 394.24,15.25 arc(393.91,15.39) 393.78,15.71 J23.I2
SAS_B2_RX2P: length 28
  BOTTOM w0.107: J24.1A4 400.14,36.78 arc(400.07,36.83) 399.99,36.82 399.97,36.81 arc(399.96,36.8) 399.94,36.79 399.76,36.6 arc(399.67,36.46) 399.63,36.3 399.63,36.03 arc(399.29,35.2) 398.46,34.86 396.67,34.86 arc(396.19,34.66) 395.99,34.18 395.99,27.38 arc(395.91,26.99) 395.69,26.66 arc(395.58,26.49) 395.54,26.29 395.54,21.04 arc(395.58,20.95) 395.67,20.92 395.68,20.92 arc(395.81,20.86) 395.87,20.73 395.87,20.51 arc(395.81,20.38) 395.69,20.33 arc(395.58,20.29) 395.54,20.18 395.54,19.37 arc(395.57,19.3) 395.65,19.27 395.68,19.27 arc(395.81,19.21) 395.87,19.08 395.87,18.78 arc(395.81,18.66) 395.69,18.61 arc(395.58,18.56) 395.54,18.46 395.54,18.18 arc(395.42,17.59) 395.08,17.08 arc(395.01,16.97) 394.98,16.83 394.98,16.56 395.18,16.37 395.18,15.96 394.98,15.76 394.98,15.43 arc(394.8,15) 394.37,14.82 394.24,14.82 arc(393.91,14.68) 393.78,14.36 J23.H2
SAS_B2_RX3N: length 46
  LYR6 w0.112: J24.1B8 397.6,33.51 arc(397.61,33.43) 397.56,33.36 397.46,33.31 arc(397.44,33.28) 397.41,33.26 arc(397.4,33.24) 397.38,33.23 397.12,32.96 arc(396.94,32.7) 396.88,32.39 arc(397.18,31.67) 397.89,31.38 402.99,31.38 arc(403.31,31.25) 403.44,30.93 403.44,10.66 arc(403.12,9.02) 402.19,7.63 398.8,4.24 arc(398.12,3.79) 397.33,3.63 395.24,3.63 arc(395.04,3.72) 394.95,3.92 394.95,6.18 arc(394.77,6.63) 394.32,6.82 394.3,6.82 arc(393.93,6.97) J23.C2
SAS_B2_RX3P: length 46.9
  LYR6 w0.112: J24.1B7 397.87,33.01 arc(397.8,33.07) 397.72,33.06 397.67,33.03 arc(397.65,33.01) 397.64,32.99 397.36,32.72 arc(397.26,32.57) 397.23,32.39 arc(397.42,31.92) 397.89,31.72 402.99,31.72 arc(403.55,31.49) 403.79,30.93 403.79,10.66 arc(403.43,8.89) 402.43,7.39 402.02,6.98 402.02,6.67 401.75,6.39 401.43,6.39 401.15,6.11 arc(401.12,6.03) 401.15,5.95 401.15,5.95 arc(401.19,5.87) 401.15,5.79 400.74,5.38 arc(400.68,5.35) 400.61,5.38 400.59,5.39 arc(400.51,5.43) 400.44,5.39 399.87,4.83 arc(399.84,4.75) 399.87,4.67 399.88,4.67 arc(399.91,4.59) 399.88,4.52 399.45,4.09 arc(399.39,4.06) 399.33,4.09 399.31,4.11 arc(399.23,4.14) 399.15,4.11 399.04,4 arc(398.25,3.47) 397.33,3.29 395.24,3.29 arc(394.79,3.48) 394.61,3.92 394.61,6.18 arc(394.52,6.39) 394.32,6.48 arc(393.94,6.32) J23.B2
SAS_B2_RX4N: length 31.7
  BOTTOM w0.107: J24.1A8 397.58,37.35 arc(397.59,37.26) 397.54,37.2 397.44,37.15 arc(397.29,37.03) 397.19,36.87 arc(396.94,36.58) 396.58,36.49 395.82,36.49 arc(395.32,36.39) 394.89,36.1 394.81,36.02 arc(394.05,34.88) 393.78,33.54 393.78,22.92 arc(393.75,22.77) 393.66,22.63 393.11,22.08 arc(392.7,21.47) 392.56,20.75 392.56,10.06 arc(392.47,9.83) 392.24,9.74 arc(391.91,9.89) 391.78,10.22 J23.E3
SAS_B2_RX4P: length 32.3
  BOTTOM w0.107: J24.1A7 397.89,36.78 arc(397.82,36.83) 397.74,36.82 397.65,36.77 arc(397.61,36.74) 397.59,36.7 arc(397.18,36.22) 396.57,36.05 395.82,36.05 arc(395.48,35.99) 395.2,35.8 395.12,35.72 arc(394.45,34.72) 394.22,33.54 394.22,22.92 arc(394.15,22.6) 393.97,22.33 393.48,21.84 arc(393.12,21.3) 392.99,20.66 392.99,18.38 arc(393.03,18.29) 393.13,18.25 393.14,18.25 arc(393.23,18.21) 393.27,18.12 393.27,17.74 arc(393.23,17.65) 393.14,17.61 393.1,17.61 arc(393.02,17.58) 392.99,17.51 392.99,10.03 arc(392.78,9.52) 392.27,9.31 arc(392.25,9.31) 392.23,9.31 392,9.31 arc(391.85,9.24) 391.78,9.08 J23.D3
SAS_B2_RX5N: length 24.4
  BOTTOM w0.107: J24.2B5 388.83,33.55 arc(388.84,33.46) 388.79,33.4 388.76,33.39 arc(388.7,33.35) 388.64,33.29 388.44,33.1 arc(388.17,32.68) 388.07,32.19 arc(388.33,31.57) 388.95,31.31 391.98,31.31 arc(392.25,31.2) 392.36,30.93 392.36,24.36 arc(392.18,23.48) 391.68,22.73 390.84,21.88 arc(390.65,21.6) 390.58,21.27 390.58,15.48 arc(390.52,15.34) 390.38,15.28 390.28,15.28 arc(390.24,15.28) 390.19,15.27 arc(389.9,15.37) 389.78,15.64 J23.I4
SAS_B2_RX5P: length 25.5
  BOTTOM w0.107: J24.2B4 389.14,32.98 arc(389.07,33.03) 388.99,33.02 388.97,33.01 arc(388.96,33) 388.94,32.99 388.75,32.79 arc(388.57,32.52) 388.5,32.19 arc(388.64,31.87) 388.95,31.74 391.98,31.74 arc(392.56,31.51) 392.79,30.93 392.79,24.36 arc(392.58,23.31) 391.99,22.42 391.14,21.58 arc(391.05,21.43) 391.02,21.27 391.02,20.12 arc(391.04,20.06) 391.11,20.03 arc(391.28,19.96) 391.35,19.79 391.35,19.57 arc(391.29,19.45) 391.17,19.39 arc(391.06,19.35) 391.02,19.24 391.02,18.58 arc(391.06,18.47) 391.17,18.43 391.19,18.43 arc(391.32,18.38) 391.37,18.25 391.37,17.95 arc(391.31,17.8) 391.17,17.74 arc(391.06,17.7) 391.02,17.59 391.02,16.96 391.21,16.76 391.21,16.39 391.02,16.2 391.02,15.48 arc(390.83,15.03) 390.38,14.84 390.28,14.84 arc(390.26,14.84) 390.23,14.84 arc(389.91,14.68) J23.H4
SAS_B2_RX6N: length 46.8
  BOTTOM w0.107: J24.2A5 388.83,37.35 arc(388.9,37.29) 388.98,37.3 389.06,37.35 arc(389.07,37.35) 389.08,37.36 389.14,37.43 arc(389.28,37.64) 389.33,37.88 arc(389.65,38.66) 390.43,38.98 391.65,38.98 arc(392.47,38.64) 392.82,37.81 392.82,36.19 arc(392.48,35.38) 391.67,35.04 390.8,35.04 arc(390.12,35.03) 389.44,35 arc(389.25,34.96) 389.07,34.89 arc(388.87,34.82) 388.65,34.8 384.62,34.8 arc(383.56,34.36) 383.12,33.29 383.12,21.09 arc(383.25,20.77) 383.57,20.64 385.88,20.64 arc(386.67,20.31) 387,19.52 387,9.92 arc(387.05,9.79) 387.18,9.74 387.36,9.74 arc(387.66,9.86) 387.78,10.16 J23.E5
SAS_B2_RX6P: length 47.5
  BOTTOM w0.107: J23.D5 387.78,8.88 arc(387.66,9.18) 387.36,9.31 387.18,9.31 arc(386.75,9.49) 386.57,9.92 386.57,17.84 arc(386.54,17.91) 386.46,17.95 386.41,17.95 arc(386.32,17.98) 386.28,18.08 386.28,18.44 arc(386.31,18.52) 386.39,18.55 arc(386.52,18.61) 386.57,18.73 386.57,19.52 arc(386.37,20) 385.88,20.2 383.57,20.2 arc(382.94,20.46) 382.68,21.09 382.68,21.25 arc(382.65,21.33) 382.57,21.36 382.48,21.36 arc(382.39,21.39) 382.35,21.48 382.35,21.81 arc(382.39,21.9) 382.48,21.93 382.57,21.93 arc(382.65,21.96) 382.68,22.04 382.68,23.76 arc(382.67,23.81) 382.65,23.85 382.5,23.99 382.5,24.57 382.65,24.72 arc(382.67,24.76) 382.68,24.81 382.68,33.29 arc(383.25,34.66) 384.62,35.23 388.65,35.23 arc(388.77,35.25) 388.89,35.28 arc(389.13,35.38) 389.38,35.43 arc(390.09,35.46) 390.8,35.47 391.67,35.47 arc(392.17,35.68) 392.38,36.19 392.38,37.81 arc(392.17,38.33) 391.65,38.54 390.43,38.54 arc(389.96,38.35) 389.77,37.88 arc(389.68,37.47) 389.45,37.12 389.39,37.06 arc(389.33,37) 389.26,36.96 389.18,36.92 arc(389.13,36.86) 389.14,36.78 J24.2A4
SAS_B2_RX7N: length 27
  LYR6 w0.112: J23.I6 385.38,15.34 arc(385.21,15.23) 385.02,15.19 384.62,15.19 arc(384.18,15.28) 383.82,15.52 arc(383.3,16.3) 383.12,17.21 383.12,19.42 arc(383.14,19.47) 383.19,19.49 383.2,19.49 arc(383.3,19.54) 383.35,19.64 383.35,20.06 arc(383.3,20.16) 383.2,20.2 arc(383.14,20.23) 383.12,20.29 383.12,21.18 arc(383.15,21.25) 383.22,21.28 arc(383.31,21.32) 383.35,21.41 383.35,21.97 arc(383.31,22.05) 383.23,22.09 383.23,22.09 arc(383.15,22.12) 383.12,22.2 383.12,22.92 arc(383.14,22.98) 383.2,23.01 arc(383.29,23.05) 383.33,23.14 383.33,23.58 arc(383.29,23.68) 383.2,23.72 arc(383.14,23.74) 383.12,23.8 383.12,24.95 383.35,25.19 383.35,25.5 383.12,25.73 383.12,29.11 383.12,29.11 arc(383.62,31.63) 385.05,33.77 arc(385.17,33.95) 385.21,34.17 385.21,34.28 arc(385.37,34.67) 385.77,34.84 386.7,34.84 arc(386.88,34.8) 387.03,34.7 387.1,34.63 arc(387.15,34.56) 387.16,34.48 387.16,34.25 arc(387.09,33.88) 386.88,33.56 386.82,33.51 arc(386.81,33.49) 386.79,33.49 386.75,33.46 arc(386.67,33.46) 386.6,33.51 J24.2B8
SAS_B2_RX7P: length 28
  LYR6 w0.112: J24.2B7 386.87,33.01 arc(386.86,33.1) 386.91,33.16 386.95,33.18 arc(387.01,33.22) 387.06,33.26 387.12,33.32 arc(387.4,33.75) 387.5,34.25 387.5,34.48 arc(387.46,34.69) 387.34,34.87 387.27,34.94 arc(387.01,35.12) 386.7,35.18 385.77,35.18 arc(385.13,34.92) 384.87,34.28 384.87,34.17 arc(384.85,34.08) 384.8,34.01 arc(383.3,31.76) 382.77,29.11 382.77,17.21 arc(382.98,16.16) 383.57,15.28 arc(384.05,14.96) 384.62,14.85 385.02,14.85 arc(385.25,14.8) 385.45,14.67 J23.H6
SAS_B2_RX8N: length 41.2
  LYR6 w0.112: J23.C6 385.78,7.33 arc(385.63,6.97) 385.27,6.82 384.44,6.82 384.4,6.86 383.94,6.86 383.9,6.82 383.24,6.82 arc(382.34,7.19) 381.97,8.09 381.97,8.54 arc(381.99,8.61) 382.05,8.63 arc(382.16,8.67) 382.2,8.78 382.2,9.04 arc(382.15,9.15) 382.05,9.19 arc(381.99,9.21) 381.97,9.27 381.97,10.62 arc(382,10.69) 382.06,10.71 arc(382.16,10.75) 382.2,10.85 382.2,11.27 arc(382.16,11.37) 382.06,11.41 arc(381.99,11.44) 381.97,11.5 381.97,12.65 arc(381.99,12.72) 382.06,12.74 arc(382.16,12.78) 382.2,12.88 382.2,13.3 arc(382.15,13.41) 382.05,13.45 arc(381.99,13.48) 381.97,13.54 381.97,14.33 arc(381.99,14.38) 382.04,14.4 arc(382.15,14.45) 382.2,14.56 382.2,14.86 arc(382.15,14.98) 382.03,15.03 arc(381.99,15.05) 381.97,15.1 381.97,31.24 arc(382.26,32.73) 383.11,34 383.86,34.75 arc(384.53,35.75) 384.76,36.92 384.76,37.03 arc(384.87,37.56) 385.16,38 385.46,38.3 arc(385.9,38.59) 386.42,38.7 arc(386.76,38.63) 387.04,38.44 387.27,38.21 arc(387.36,37.99) 387.27,37.77 386.8,37.3 arc(386.79,37.29) 386.78,37.28 386.75,37.26 arc(386.67,37.26) 386.6,37.31 J24.2A8
SAS_B2_RX8P: length 42.1
  LYR6 w0.112: J24.2A7 386.87,36.81 arc(386.86,36.9) 386.91,36.96 386.94,36.98 arc(387,37.01) 387.05,37.05 387.51,37.52 arc(387.71,37.99) 387.51,38.45 387.28,38.68 arc(386.89,38.95) 386.42,39.04 arc(385.77,38.91) 385.22,38.54 384.92,38.24 arc(384.55,37.69) 384.42,37.03 384.42,36.92 arc(384.21,35.88) 383.62,34.99 382.87,34.24 arc(381.95,32.86) 381.62,31.24 381.62,8.09 arc(382.1,6.95) 383.24,6.48 385.27,6.48 arc(385.63,6.33) 385.78,5.97 J23.B6
SAS_B2_TX1N: length 23.7
  LYR6 w0.112: J24.1D5 399.85,25.91 arc(399.86,25.83) 399.81,25.76 399.72,25.71 arc(399.67,25.68) 399.61,25.63 399.19,25.21 arc(398.78,24.59) 398.63,23.86 398.63,7.05 arc(398.57,6.72) 398.38,6.44 398,6.06 arc(397.39,5.65) 396.68,5.51 396.25,5.51 arc(395.92,5.65) 395.78,5.98 J23.B1
SAS_B2_TX1P: length 24.6
  LYR6 w0.112: J23.A1 395.78,4.7 arc(395.92,5.03) 396.25,5.17 396.68,5.17 arc(397.53,5.34) 398.24,5.82 398.62,6.2 arc(398.89,6.59) 398.98,7.05 398.98,7.32 arc(399,7.38) 399.07,7.4 arc(399.16,7.44) 399.2,7.54 399.2,7.85 arc(399.17,7.93) 399.09,7.96 399.09,7.96 arc(399.01,8) 398.98,8.07 398.98,8.89 arc(399.01,8.97) 399.09,9 arc(399.17,9.04) 399.2,9.12 399.2,9.5 arc(399.16,9.6) 399.07,9.64 arc(399,9.67) 398.98,9.73 398.98,10.61 399.17,10.8 399.17,11.11 398.98,11.3 398.98,23.86 arc(399.1,24.46) 399.44,24.97 399.86,25.39 arc(399.87,25.4) 399.88,25.41 399.97,25.46 arc(400.05,25.47) 400.12,25.41 J24.1D4
SAS_B2_TX2N: length 23.1
  BOTTOM w0.107: J24.1C5 399.83,29.75 arc(399.84,29.66) 399.79,29.6 399.71,29.56 arc(399.64,29.52) 399.58,29.46 399.57,29.45 arc(399.27,29.08) 399.08,28.65 arc(399.38,27.8) 400.2,27.44 400.97,27.44 arc(401.81,27.28) 402.52,26.8 402.99,26.33 arc(403.3,25.87) 403.4,25.34 403.4,23.3 arc(402.91,20.81) 401.49,18.69 396.83,14.03 arc(396.75,13.98) 396.65,13.96 396.26,13.96 arc(395.92,14.1) J23.H1
SAS_B2_TX2P: length 23.6
  BOTTOM w0.107: J24.1C4 400.14,29.18 arc(400.07,29.23) 399.99,29.22 399.91,29.18 arc(399.9,29.17) 399.89,29.16 399.87,29.14 arc(399.66,28.87) 399.51,28.57 arc(399.71,28.08) 400.2,27.88 400.97,27.88 arc(401.98,27.68) 402.83,27.11 403.3,26.64 arc(403.7,26.04) 403.84,25.34 403.84,23.3 arc(403.31,20.64) 401.8,18.39 398.94,15.52 398.94,15.28 398.64,14.99 398.4,14.99 398.11,14.7 398.11,14.4 397.87,14.16 397.57,14.16 397.14,13.73 arc(396.91,13.58) 396.65,13.52 396.26,13.52 arc(395.92,13.38) J23.G1
SAS_B2_TX3N: length 18.3
  LYR6 w0.112: J24.1D8 397.6,25.91 arc(397.61,25.83) 397.56,25.76 397.47,25.71 arc(397.42,25.68) 397.36,25.63 396.94,25.21 arc(396.59,24.98) 396.17,24.89 396.07,24.89 arc(395.51,24.78) 395.04,24.46 394.97,24.39 arc(394.7,24) 394.61,23.53 394.61,11.29 arc(394.52,11.08) 394.32,11 394.14,11 arc(393.89,11.1) 393.78,11.36 J23.F2
SAS_B2_TX3P: length 18.8
  LYR6 w0.112: J24.1D7 397.87,25.41 arc(397.8,25.47) 397.72,25.46 397.63,25.41 arc(397.62,25.4) 397.61,25.39 397.19,24.97 arc(396.72,24.66) 396.17,24.55 396.07,24.55 arc(395.64,24.46) 395.28,24.22 395.21,24.15 arc(395.02,23.87) 394.95,23.53 394.95,18.54 395.01,18.47 395.01,18.12 394.95,18.06 394.95,17.36 arc(394.98,17.29) 395.06,17.25 arc(395.15,17.22) 395.18,17.13 395.18,16.8 arc(395.14,16.7) 395.05,16.67 arc(394.98,16.64) 394.95,16.57 394.95,11.29 arc(394.77,10.84) 394.32,10.66 394.14,10.66 arc(393.89,10.55) 393.78,10.3 J23.E2
SAS_B2_TX4N: length 19.2
  LYR6 w0.112: J24.1C8 397.6,29.71 arc(397.61,29.63) 397.56,29.56 397.52,29.54 arc(397.46,29.5) 397.41,29.46 396.89,28.94 arc(396.78,28.87) 396.65,28.84 arc(396.35,28.78) 396.09,28.61 395.32,27.84 arc(393.3,24.82) 392.59,21.25 392.59,14.24 arc(392.49,14) 392.26,13.91 arc(391.92,14.05) 391.78,14.39 J23.H3
SAS_B2_TX4P: length 19.8
  LYR6 w0.112: J24.1C7 397.87,29.21 arc(397.8,29.27) 397.72,29.26 397.68,29.24 arc(397.66,29.23) 397.65,29.22 397.13,28.7 arc(396.91,28.55) 396.65,28.5 arc(396.48,28.46) 396.33,28.36 395.56,27.6 arc(393.62,24.69) 392.93,21.25 392.93,19.89 393.03,19.78 393.03,19.32 392.93,19.22 392.93,18.49 arc(392.96,18.42) 393.03,18.39 arc(393.14,18.35) 393.19,18.23 393.19,17.91 arc(393.14,17.79) 393.02,17.74 arc(392.96,17.72) 392.93,17.66 392.93,14.24 arc(392.74,13.76) 392.26,13.56 arc(391.92,13.42) 391.78,13.08 J23.G3
SAS_B2_TX5N: length 17.3
  LYR6 w0.112: J24.2D5 388.85,25.91 arc(388.86,25.83) 388.81,25.76 388.77,25.74 arc(388.71,25.7) 388.66,25.66 388.53,25.53 arc(388.3,25.19) 388.22,24.78 388.22,24.6 arc(388.45,23.47) 389.08,22.52 arc(390.19,20.86) 390.58,18.9 390.58,11.26 arc(390.51,11.09) 390.33,11.01 390.31,11.01 arc(389.93,11.17) J23.F4
SAS_B2_TX5P: length 17.7
  LYR6 w0.112: J24.2D4 389.12,25.41 arc(389.05,25.47) 388.97,25.46 388.93,25.44 arc(388.91,25.43) 388.9,25.42 388.78,25.29 arc(388.62,25.06) 388.56,24.78 388.56,24.6 arc(388.76,23.6) 389.33,22.76 arc(390.51,20.99) 390.93,18.9 390.93,18.14 390.96,18.11 390.96,17.68 390.93,17.64 390.93,17.23 arc(390.95,17.16) 391.02,17.13 arc(391.12,17.09) 391.16,17 391.16,16.61 arc(391.11,16.5) 391.01,16.46 arc(390.95,16.44) 390.93,16.38 390.93,11.26 arc(390.75,10.84) 390.33,10.67 390.31,10.67 arc(389.93,10.51) J23.E4
SAS_B2_TX6N: length 31.8
  BOTTOM w0.107: J24.2C5 388.83,29.75 arc(388.84,29.66) 388.79,29.6 388.69,29.55 arc(388.51,29.41) 388.38,29.21 arc(388.29,29.05) 388.17,28.9 388.03,28.76 arc(387.79,28.39) 387.7,27.96 387.7,27.9 arc(387.64,27.76) 387.5,27.7 386.37,27.7 arc(385.86,27.6) 385.43,27.31 385.15,27.03 arc(384.47,26.02) 384.23,24.83 384.23,23.2 arc(384.37,22.52) 384.75,21.95 384.77,21.93 arc(385.13,21.69) 385.57,21.6 387.94,21.6 arc(388.37,21.42) 388.55,20.99 388.55,5.75 arc(388.49,5.61) 388.35,5.55 388.22,5.55 arc(387.91,5.68) 387.78,5.99 J23.B5
SAS_B2_TX6P: length 32.7
  BOTTOM w0.107: J24.2C4 389.14,29.18 arc(389.07,29.23) 388.99,29.22 388.9,29.17 arc(388.83,29.12) 388.78,29.04 arc(388.65,28.8) 388.47,28.59 388.34,28.45 arc(388.19,28.23) 388.13,27.96 388.13,27.9 arc(387.95,27.45) 387.5,27.27 386.37,27.27 arc(386.03,27.2) 385.74,27.01 385.45,26.72 arc(384.87,25.85) 384.67,24.83 384.67,23.2 arc(384.77,22.69) 385.06,22.25 385.07,22.24 arc(385.3,22.09) 385.57,22.03 387.94,22.03 arc(388.68,21.73) 388.99,20.99 388.99,19.77 arc(389.03,19.67) 389.14,19.62 389.16,19.62 arc(389.27,19.58) 389.31,19.47 389.31,19.12 arc(389.28,19.04) 389.21,19.01 389.11,19.01 arc(389.02,18.97) 388.99,18.88 388.99,18.47 arc(389.01,18.4) 389.08,18.38 arc(389.23,18.32) 389.29,18.17 389.29,17.94 arc(389.23,17.8) 389.09,17.74 389.08,17.74 arc(389.01,17.71) 388.99,17.65 388.99,5.75 arc(388.8,5.3) 388.35,5.12 388.22,5.12 arc(387.91,4.99) 387.78,4.67 J23.A5
SAS_B2_TX7N: length 14.8
  LYR6 w0.112: J24.2D8 386.6,25.91 arc(386.61,25.83) 386.56,25.76 386.52,25.74 arc(386.46,25.7) 386.41,25.66 386.13,25.38 arc(385.99,25.16) 385.93,24.9 385.93,24.88 arc(386.04,24.35) 386.34,23.9 386.56,23.68 arc(386.74,23.42) 386.8,23.1 386.8,22.96 arc(386.89,22.52) 387.14,22.15 388.43,20.85 arc(388.55,20.68) 388.59,20.47 388.59,14.08 arc(388.54,13.96) 388.41,13.91 388.27,13.91 arc(387.92,14.05) 387.78,14.4 J23.H5
